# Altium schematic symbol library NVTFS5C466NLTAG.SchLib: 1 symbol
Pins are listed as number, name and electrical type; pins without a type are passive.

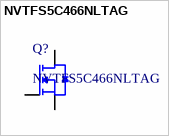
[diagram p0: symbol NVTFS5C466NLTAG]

## NVTFS5C466NLTAG
designator Q?
N-Channel 40 V 51A (Tc) 38W (Tc) Surface Mount 8-WDFN (3.3x3.3); Manufacturer_Name: onsemi
footprint WDFN8_3P3X3P3_ONS
pins: 1 S, 2 S, 3 S, 4 G, 5 D, 6 D, 7 D, 8 D, 9 D, 10 D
